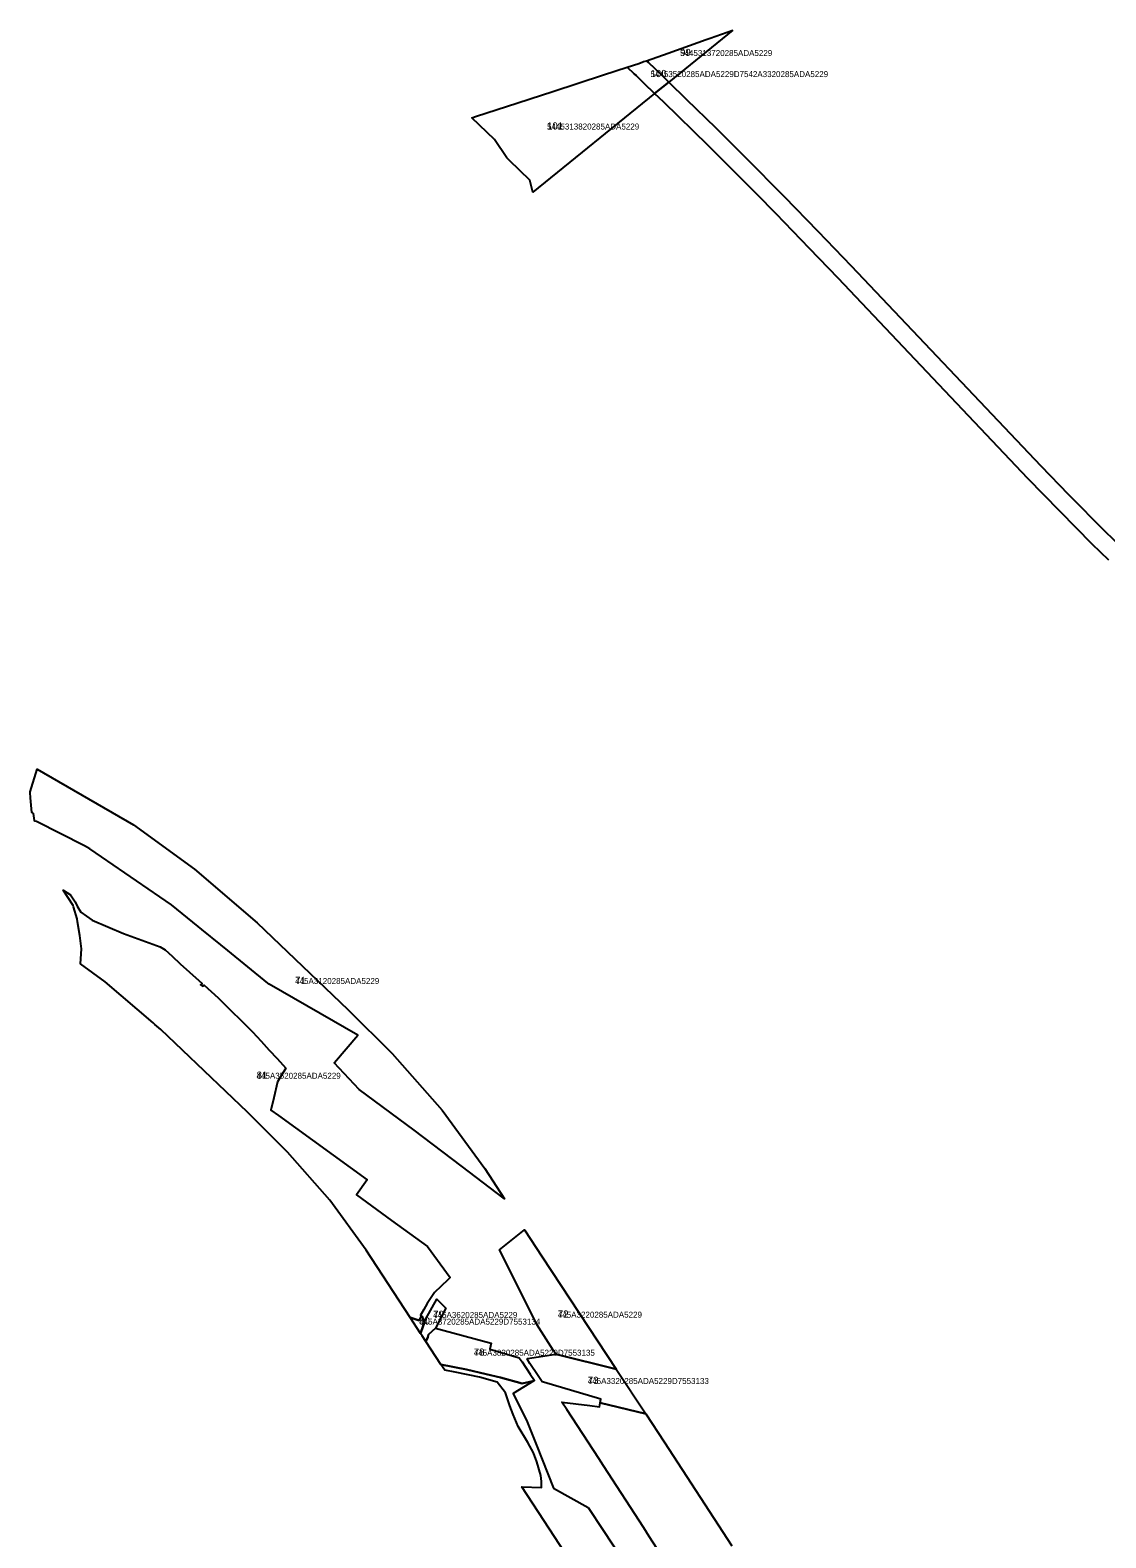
# Model space of a CAD drawing. Extents: x -545623 to -541713, y -1153152 to -1149975.
# Drawn here: x -544030 to -543132, y -1151332 to -1150072 of the extents above; entities that cross this region are included whole.
import ezdxf

# ---------------------------------------------------------------- set-up
doc = ezdxf.new("R2010")
doc.units = 0
for name, color, linetype in [('96120023', 7, 'Continuous'), ('96140023', 7, 'Continuous'), ('ID_VPO', 7, 'Continuous'), ('ID_VPS', 7, 'Continuous')]:
    doc.layers.add(name, color=color, linetype=linetype)

msp = doc.modelspace()

# ---------------------------------------------------------------- linework, layer by layer
at = {"layer": '96120023'}
for points in [[(-543443.3, -1150072), (-543496.8, -1150115.3), (-543502.9, -1150109.4), (-543513.7, -1150099), (-543515.4, -1150097.5), (-543497.2, -1150091.1), (-543479.5, -1150084.8), (-543465.5, -1150079.8), (-543462.1, -1150078.6)], [(-543513.7, -1150099), (-543502.9, -1150109.4), (-543496.8, -1150115.3), (-543508.6, -1150124.8), (-543517.5, -1150116.3), (-543524.1, -1150109.9), (-543525.6, -1150108.5), (-543531.4, -1150102.9), (-543521.8, -1150099.8), (-543521.1, -1150099.5), (-543518.9, -1150098.7), (-543517.8, -1150098.3), (-543517.7, -1150098.3), (-543517.6, -1150098.3), (-543515.4, -1150097.5)], [(-543551.2, -1150109.3), (-543531.4, -1150102.9), (-543525.6, -1150108.5), (-543524.1, -1150109.9), (-543517.5, -1150116.3), (-543508.6, -1150124.8), (-543610.3, -1150207.2), (-543612.7, -1150197.2), (-543629.9, -1150180.9), (-543632.1, -1150178.7), (-543642.4, -1150163.3), (-543661.2, -1150145.1), (-543657.2, -1150143.8), (-543632.2, -1150135.7), (-543593.5, -1150123.1)], [(-543831.5, -1150868.1), (-543831.5, -1150868.1), (-543865, -1150840.9), (-543870.9, -1150836.1), (-543886.6, -1150823.4), (-543889.8, -1150820.9), (-543912.1, -1150802.8), (-543980.2, -1150755.9), (-543984.6, -1150753.6), (-544024.7, -1150733.1), (-544026.3, -1150733), (-544026.4, -1150732.2), (-544027.2, -1150726.5), (-544028.2, -1150725.9), (-544028.6, -1150725.7), (-544029.7, -1150713.4), (-544030, -1150709), (-544030.1, -1150708.5), (-544024.2, -1150689.3), (-543943.7, -1150735.8), (-543892.9, -1150773), (-543840.5, -1150817.9), (-543764.8, -1150890.1), (-543727.8, -1150927), (-543686, -1150974.3), (-543650.5, -1151023.2), (-543634, -1151048.5), (-543670.1, -1151020.9), (-543709.4, -1150991), (-543755.3, -1150957.1), (-543776.2, -1150934.7), (-543776, -1150934.4), (-543756.5, -1150911.7), (-543830.4, -1150869)], [(-543779.7, -1151049.5), (-543815.3, -1151009.3), (-543848.6, -1150976), (-543920.9, -1150907), (-543925.9, -1150902.8), (-543927.4, -1150901.5), (-543967.5, -1150867.2), (-543988, -1150852.1), (-543987.1, -1150839.5), (-543988.5, -1150828.3), (-543990.5, -1150816.9), (-543990.9, -1150814.5), (-543993.8, -1150804.5), (-543994.1, -1150803.4), (-544002.6, -1150790.4), (-543996.5, -1150794.3), (-543992.6, -1150800.4), (-543990.7, -1150803.9), (-543987.9, -1150808.9), (-543978.4, -1150815.7), (-543952.2, -1150826.6), (-543921.6, -1150838), (-543917.4, -1150840.5), (-543911.6, -1150845.7), (-543904.7, -1150852), (-543889.2, -1150866), (-543886.4, -1150868.5), (-543887.8, -1150869.6), (-543886.2, -1150870.8), (-543884.9, -1150869.8), (-543873.2, -1150880.5), (-543862.7, -1150890.9), (-543853.7, -1150899.7), (-543844.4, -1150908.8), (-543837.1, -1150916.8), (-543830.4, -1150924.1), (-543823.8, -1150931.3), (-543816.6, -1150939.1), (-543823.4, -1150950.7), (-543826.7, -1150963.9), (-543829.2, -1150974.2), (-543822.7, -1150978.9), (-543748.7, -1151032.5), (-543757.5, -1151045.1), (-543728.2, -1151066.5), (-543698.3, -1151088.2), (-543679.4, -1151114.2), (-543681.4, -1151116.1), (-543692.3, -1151126.7), (-543698.6, -1151135.9), (-543701.3, -1151140.8), (-543703.3, -1151144.3), (-543704, -1151145.7), (-543703.3, -1151146.2), (-543705.3, -1151150.2), (-543712.7, -1151147.5), (-543749.4, -1151091.2)], [(-543593.2, -1151174.9), (-543593.2, -1151174.9), (-543607, -1151153.5), (-543634.9, -1151097.4), (-543638.1, -1151091.1), (-543617.2, -1151074.3), (-543602.4, -1151097), (-543540.7, -1151190.6), (-543591.1, -1151178.2)], [(-543703.5, -1151159.2), (-543701.1, -1151152.2), (-543699.7, -1151148.7), (-543690.5, -1151132.2), (-543682.9, -1151139.8), (-543691.5, -1151156.4), (-543697.4, -1151161.9), (-543698.1, -1151163.9), (-543699.6, -1151167.6), (-543702.8, -1151162.8), (-543704.1, -1151160.8)], [(-543704.1, -1151160.8), (-543712.7, -1151147.5), (-543705.3, -1151150.2), (-543703.3, -1151146.2), (-543702.6, -1151146.7), (-543700.9, -1151151.1), (-543701.1, -1151152.2), (-543703.5, -1151159.2)], [(-543665.7, -1151191), (-543687, -1151186.8), (-543699.6, -1151167.6), (-543698.1, -1151163.9), (-543697.4, -1151161.9), (-543691.5, -1151156.4), (-543645.1, -1151169.1), (-543646.1, -1151174), (-543622.4, -1151181), (-543621.6, -1151181.2), (-543619.2, -1151184.7), (-543612.4, -1151195), (-543608.9, -1151200.3), (-543609.4, -1151200.6), (-543619.3, -1151202.6), (-543637.2, -1151197.6), (-543649.2, -1151195)], [(-543602.4, -1151201.4), (-543602.4, -1151201.4), (-543605.9, -1151196.2), (-543612.7, -1151185.9), (-543615.1, -1151182.2), (-543614.6, -1151181.8), (-543591.1, -1151178.2), (-543540.7, -1151190.6), (-543516, -1151228), (-543554.1, -1151218.9), (-543553.4, -1151215.9), (-543601.5, -1151201.6)]]:
    msp.add_lwpolyline(points, close=True, dxfattribs=at)
for points in [[(-543129.2, -1150514.8), (-543143.1, -1150501.3), (-543196.8, -1150446.5), (-543355.3, -1150279.3), (-543379.2, -1150254.3), (-543407.2, -1150225.5), (-543423.3, -1150209.1), (-543443.6, -1150188.7), (-543463.9, -1150168.4), (-543500.9, -1150132.2), (-543508.6, -1150124.8), (-543496.8, -1150115.3), (-543482.2, -1150129.5), (-543457.5, -1150153.7), (-543432.9, -1150178.1), (-543400.5, -1150210.9), (-543372.4, -1150239.8), (-543344.5, -1150269), (-543186, -1150436), (-543163, -1150460), (-543132.5, -1150490.7), (-543118.8, -1150504)], [(-543544, -1151404.6), (-543601.1, -1151317.1), (-543619.6, -1151288.9), (-543603, -1151289.5), (-543603, -1151284.5), (-543603.6, -1151279.7), (-543607, -1151268.1), (-543609.7, -1151260.5), (-543614.4, -1151251.9), (-543622.4, -1151238.6), (-543626.8, -1151228.6), (-543629.5, -1151221.4), (-543633.2, -1151210.5), (-543640, -1151201.5), (-543654.8, -1151197.3), (-543654.9, -1151197.3), (-543675.2, -1151193.3), (-543683.8, -1151191.6), (-543687, -1151186.8), (-543665.7, -1151191), (-543649.2, -1151195), (-543637.2, -1151197.6), (-543619.3, -1151202.6), (-543609.4, -1151200.6), (-543626.8, -1151211.1), (-543615.1, -1151234.8), (-543607.1, -1151254.3), (-543592.9, -1151290.1), (-543564.1, -1151306.3), (-543551.5, -1151325.3), (-543528.4, -1151360.2)], [(-543492.4, -1151362.2), (-543513, -1151330.5), (-543517.6, -1151323.4), (-543551.4, -1151271.5), (-543555.3, -1151265.5), (-543582, -1151224.4), (-543586, -1151218.3), (-543562.6, -1151221.1), (-543554.5, -1151222.1), (-543554.1, -1151218.9), (-543516, -1151228), (-543500.7, -1151251.3), (-543444, -1151338.3)]]:
    msp.add_lwpolyline(points, dxfattribs=at)
at = {"layer": '96140023'}
for points in [[(-543704.1, -1151160.8), (-543712.7, -1151147.5), (-543705.3, -1151150.2), (-543703.3, -1151146.2), (-543702.6, -1151146.7), (-543700.9, -1151151.1), (-543701.1, -1151152.2), (-543703.5, -1151159.2)], [(-543649.2, -1151195), (-543665.7, -1151191), (-543687, -1151186.8), (-543699.6, -1151167.6), (-543698.1, -1151163.9), (-543697.4, -1151161.9), (-543691.5, -1151156.4), (-543645.1, -1151169.1), (-543646.1, -1151174), (-543622.4, -1151181), (-543621.6, -1151181.2), (-543619.2, -1151184.7), (-543612.4, -1151195), (-543608.9, -1151200.3), (-543609.4, -1151200.6), (-543619.3, -1151202.6), (-543637.2, -1151197.6)], [(-543602.4, -1151201.4), (-543602.4, -1151201.4), (-543605.9, -1151196.2), (-543612.7, -1151185.9), (-543615.1, -1151182.2), (-543614.6, -1151181.8), (-543591.1, -1151178.2), (-543540.7, -1151190.6), (-543516, -1151228), (-543554.1, -1151218.9), (-543553.4, -1151215.9), (-543601.5, -1151201.6)]]:
    msp.add_lwpolyline(points, close=True, dxfattribs=at)

# ---------------------------------------------------------------- texts
at = {"layer": '96120023'}
for s, p in [('5445313720285ADA5229', (-543487.3, -1150093.6)), ('54453520285ADA5229D7542A3320285ADA5229', (-543512, -1150111.2)), ('5445313820285ADA5229', (-543598.4, -1150155)), ('445A3120285ADA5229', (-543808.8, -1150868.9)), ('445A3520285ADA5229', (-543841, -1150948.1)), ('445A3620285ADA5229', (-543693.5, -1151147.9)), ('445A3220285ADA5229', (-543589.4, -1151147.7)), ('445A3720285ADA5229D7553134', (-543705.2, -1151153.5)), ('445A3820285ADA5229D7553135', (-543659.6, -1151179.5)), ('445A3320285ADA5229D7553133', (-543564.4, -1151203.1))]:
    msp.add_text(s, height=5, rotation=360, dxfattribs=at).set_placement(p)
at = {"layer": '96140023'}
for s, p in [('445A3720285ADA5229D7553134', (-543705.2, -1151153.5)), ('445A3820285ADA5229D7553135', (-543659.6, -1151179.5)), ('445A3320285ADA5229D7553133', (-543564.4, -1151203.1))]:
    msp.add_text(s, height=5, rotation=360, dxfattribs=at).set_placement(p)
at = {"layer": 'ID_VPO'}
for s, rotation, p in [('80', 0, (-543705.2, -1151153.5)), ('78', 360, (-543659.6, -1151179.5))]:
    msp.add_text(s, height=6, rotation=rotation, dxfattribs=at).set_placement(p)
msp.add_text('73', height=6, dxfattribs=at).set_placement((-543564.4, -1151203.1))
at = {"layer": 'ID_VPS'}
for s, rotation, p in [('99', 0, (-543487.3, -1150093.6)), ('100', 360, (-543512, -1150111.2)), ('101', 0, (-543598.4, -1150155)), ('71', 0, (-543808.8, -1150868.9)), ('81', 0, (-543841, -1150948.1)), ('79', 0, (-543693.5, -1151147.9)), ('72', 0, (-543589.4, -1151147.7)), ('80', 0, (-543705.2, -1151153.5)), ('78', 360, (-543659.6, -1151179.5))]:
    msp.add_text(s, height=6, rotation=rotation, dxfattribs=at).set_placement(p)
msp.add_text('73', height=6, dxfattribs=at).set_placement((-543564.4, -1151203.1))

doc.saveas('drawing.dxf')
